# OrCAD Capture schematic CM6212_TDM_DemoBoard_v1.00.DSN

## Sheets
1 04.CS8406: size Custom; title: CS8406; rev: V100; company: C-MEDIA ELECTRONICS Inc.; note: CMA143; note: 6F., 100, Sec. 4, Civil Boulevard, Taipei, Taiwan, R.O.C.
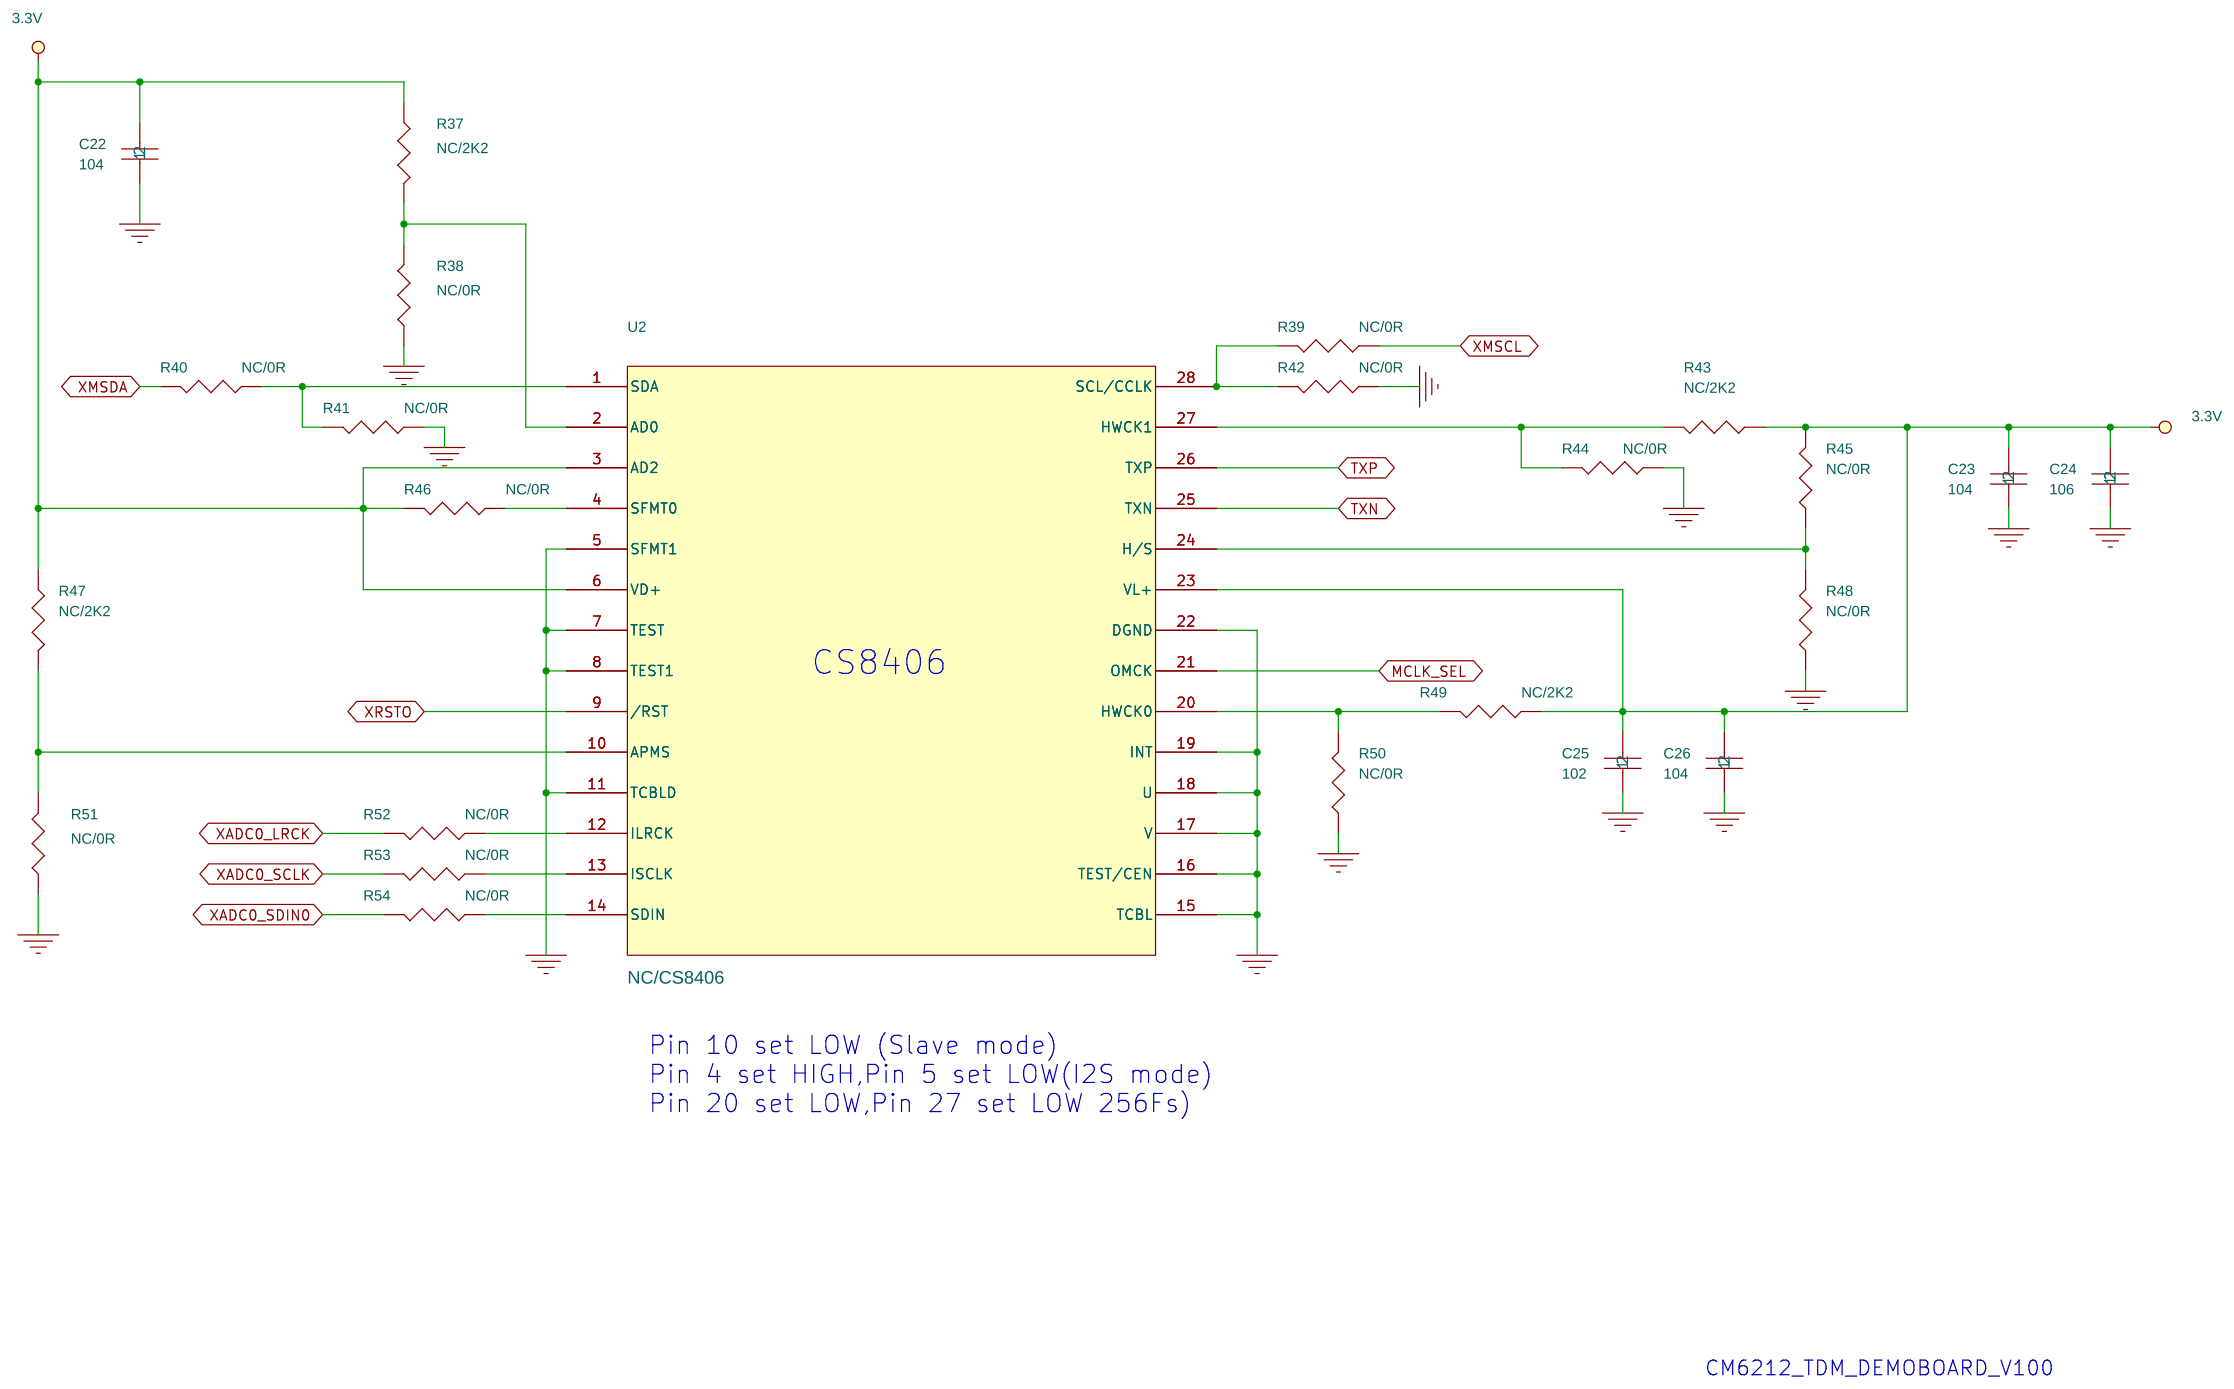
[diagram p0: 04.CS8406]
2 01.FUNCTIONAL BLOCK: title: FUNCTIONAL BLOCK; note: Function block
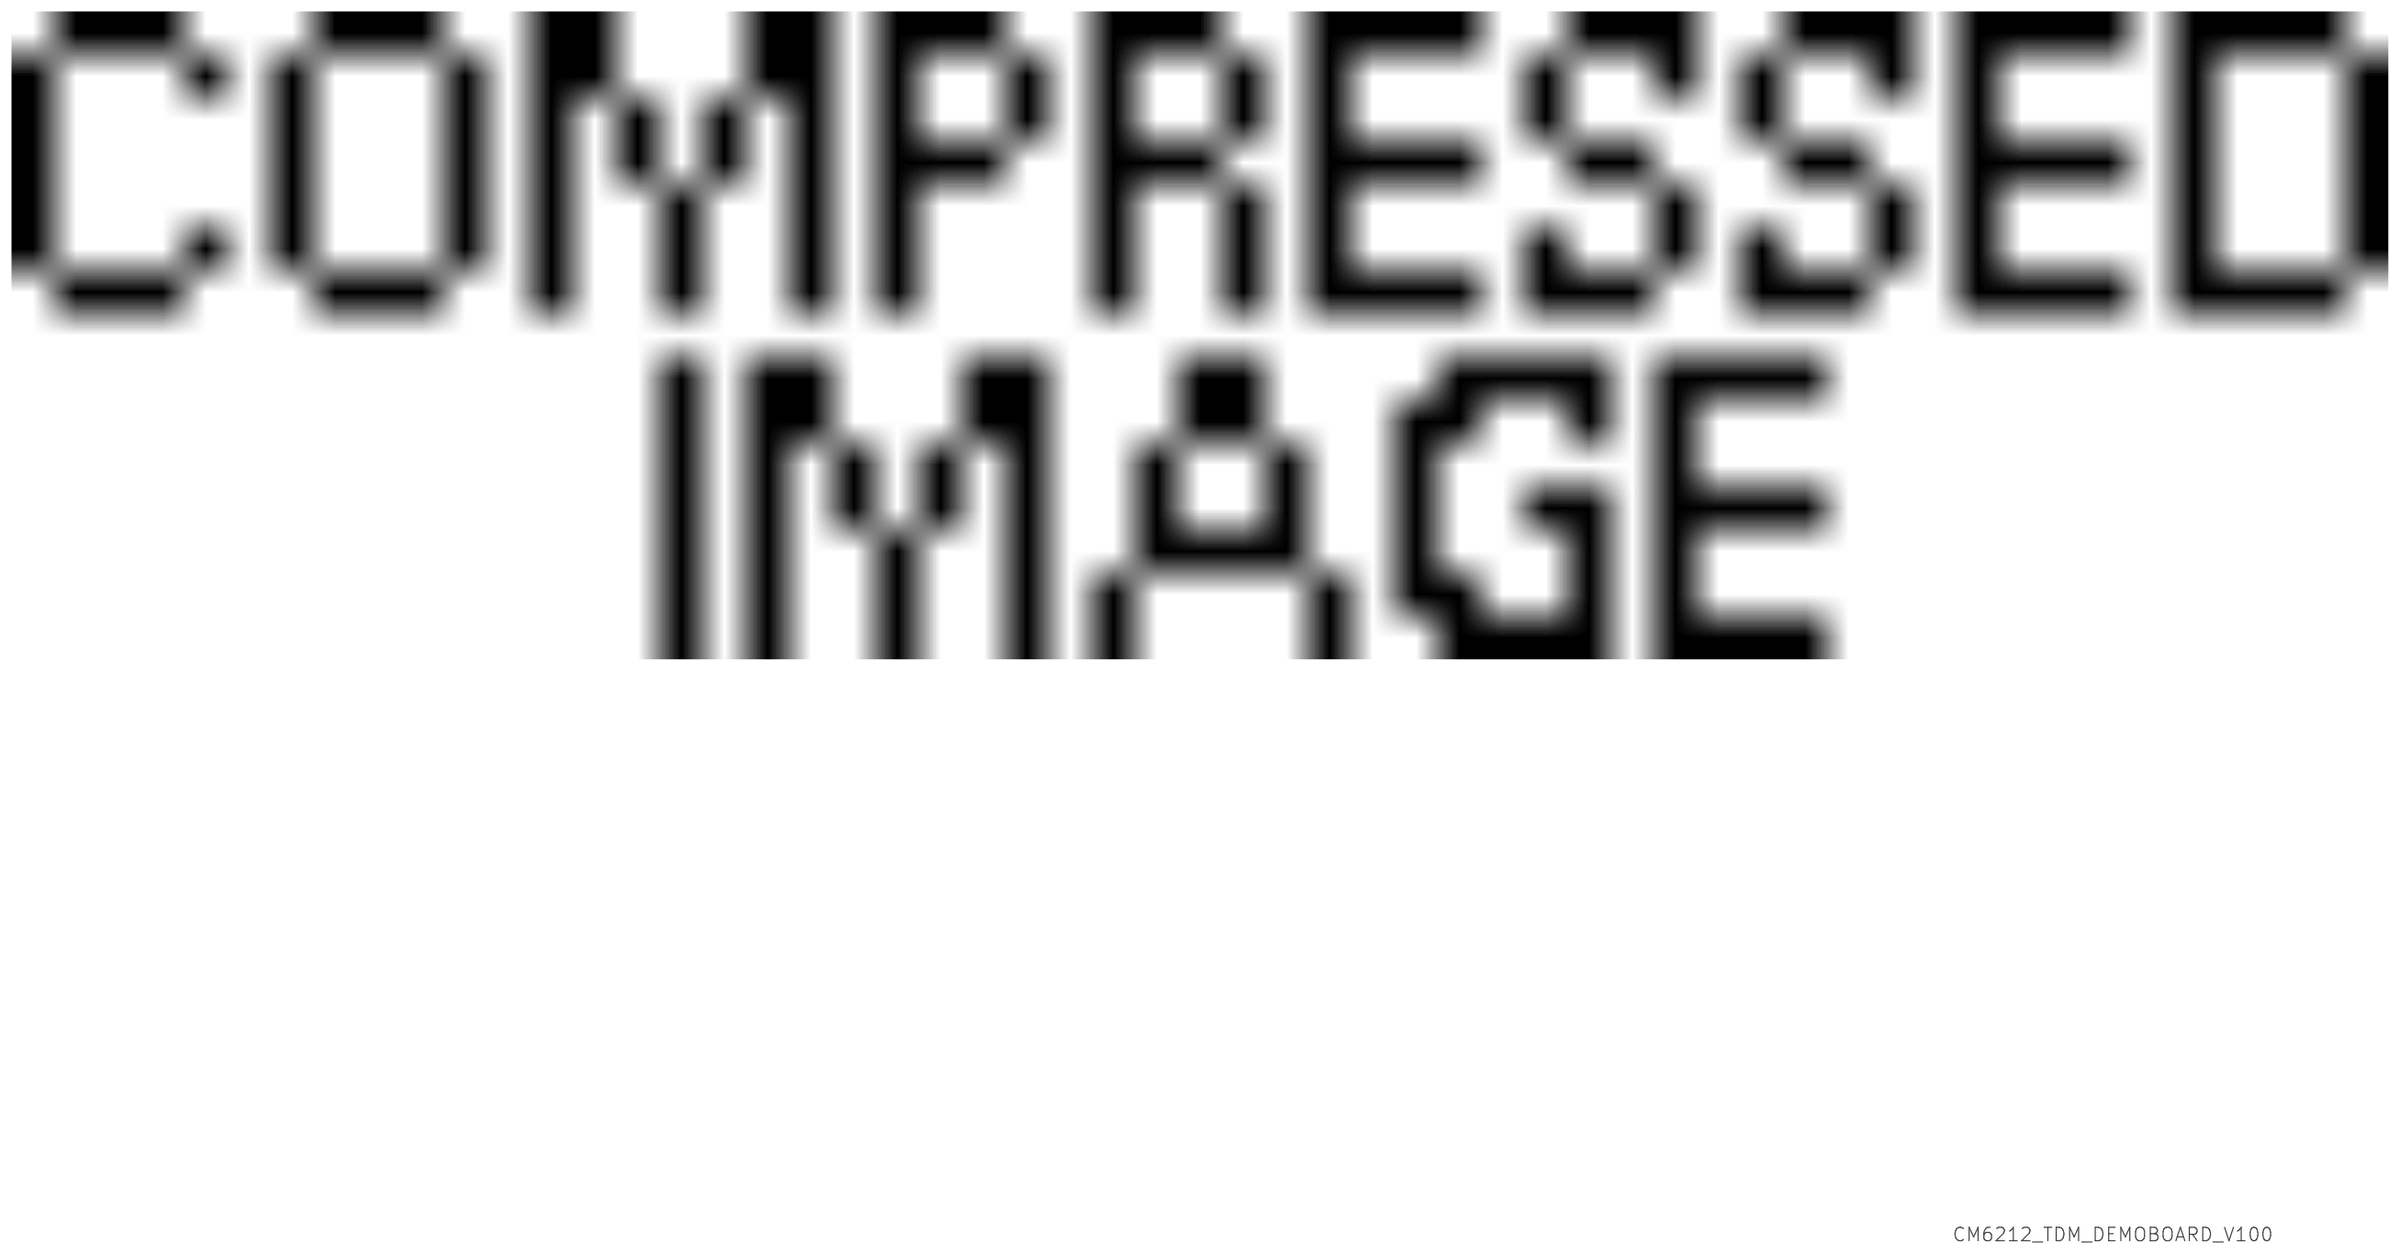
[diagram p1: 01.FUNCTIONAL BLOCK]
3 02.RELEASE NOTE: title: RELEASE NOTE; note: Placement
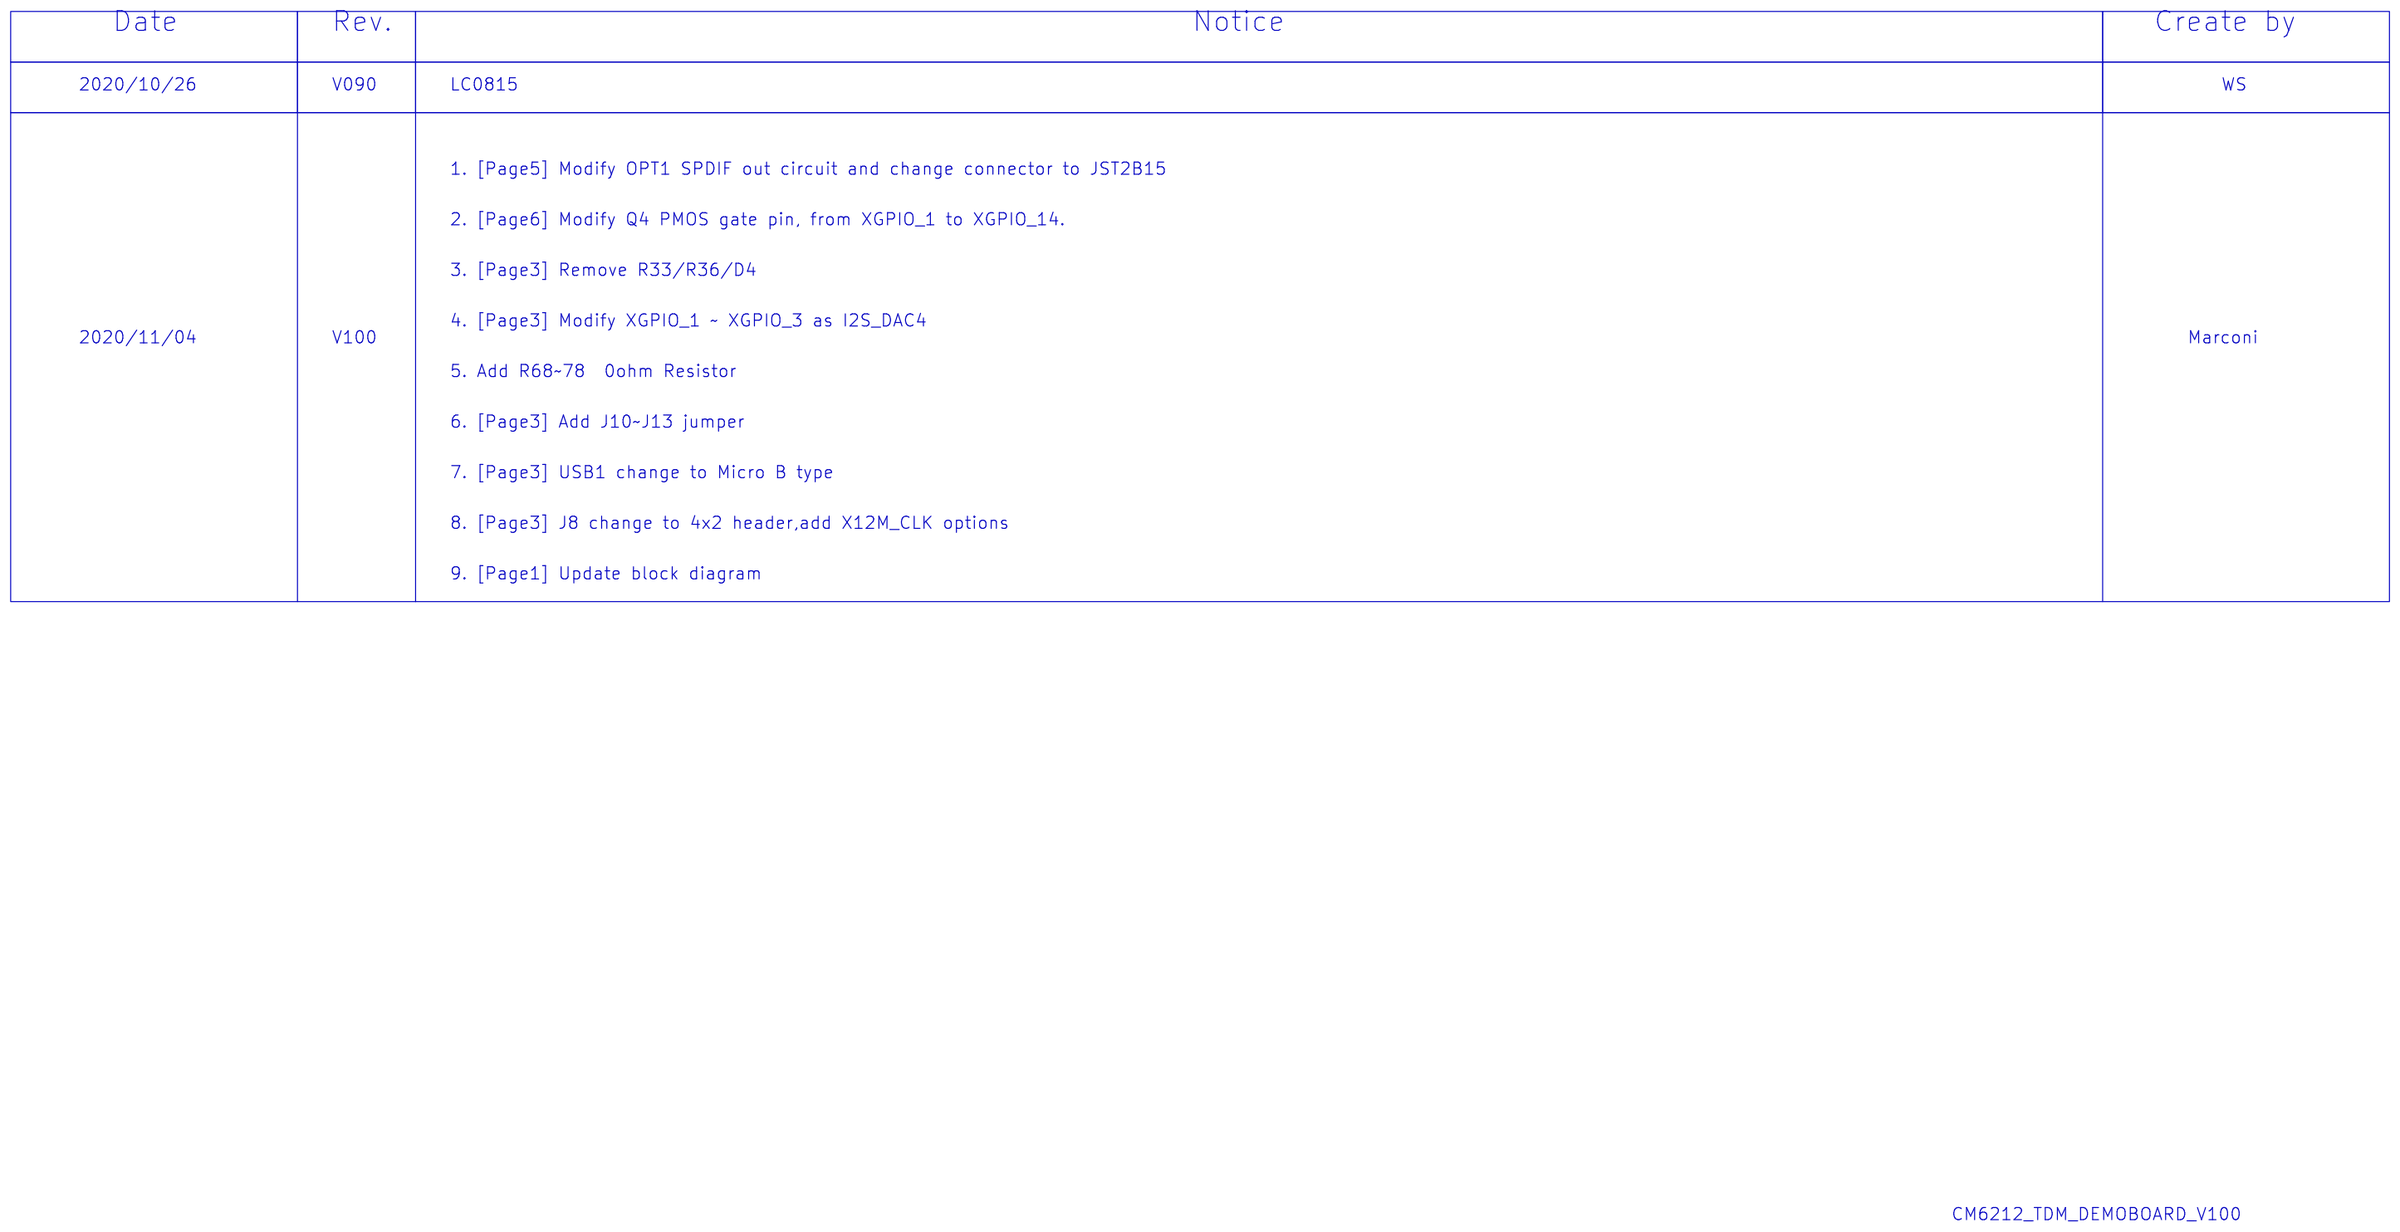
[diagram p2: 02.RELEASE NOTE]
4 03.CM6212: size Custom; title: CM6212
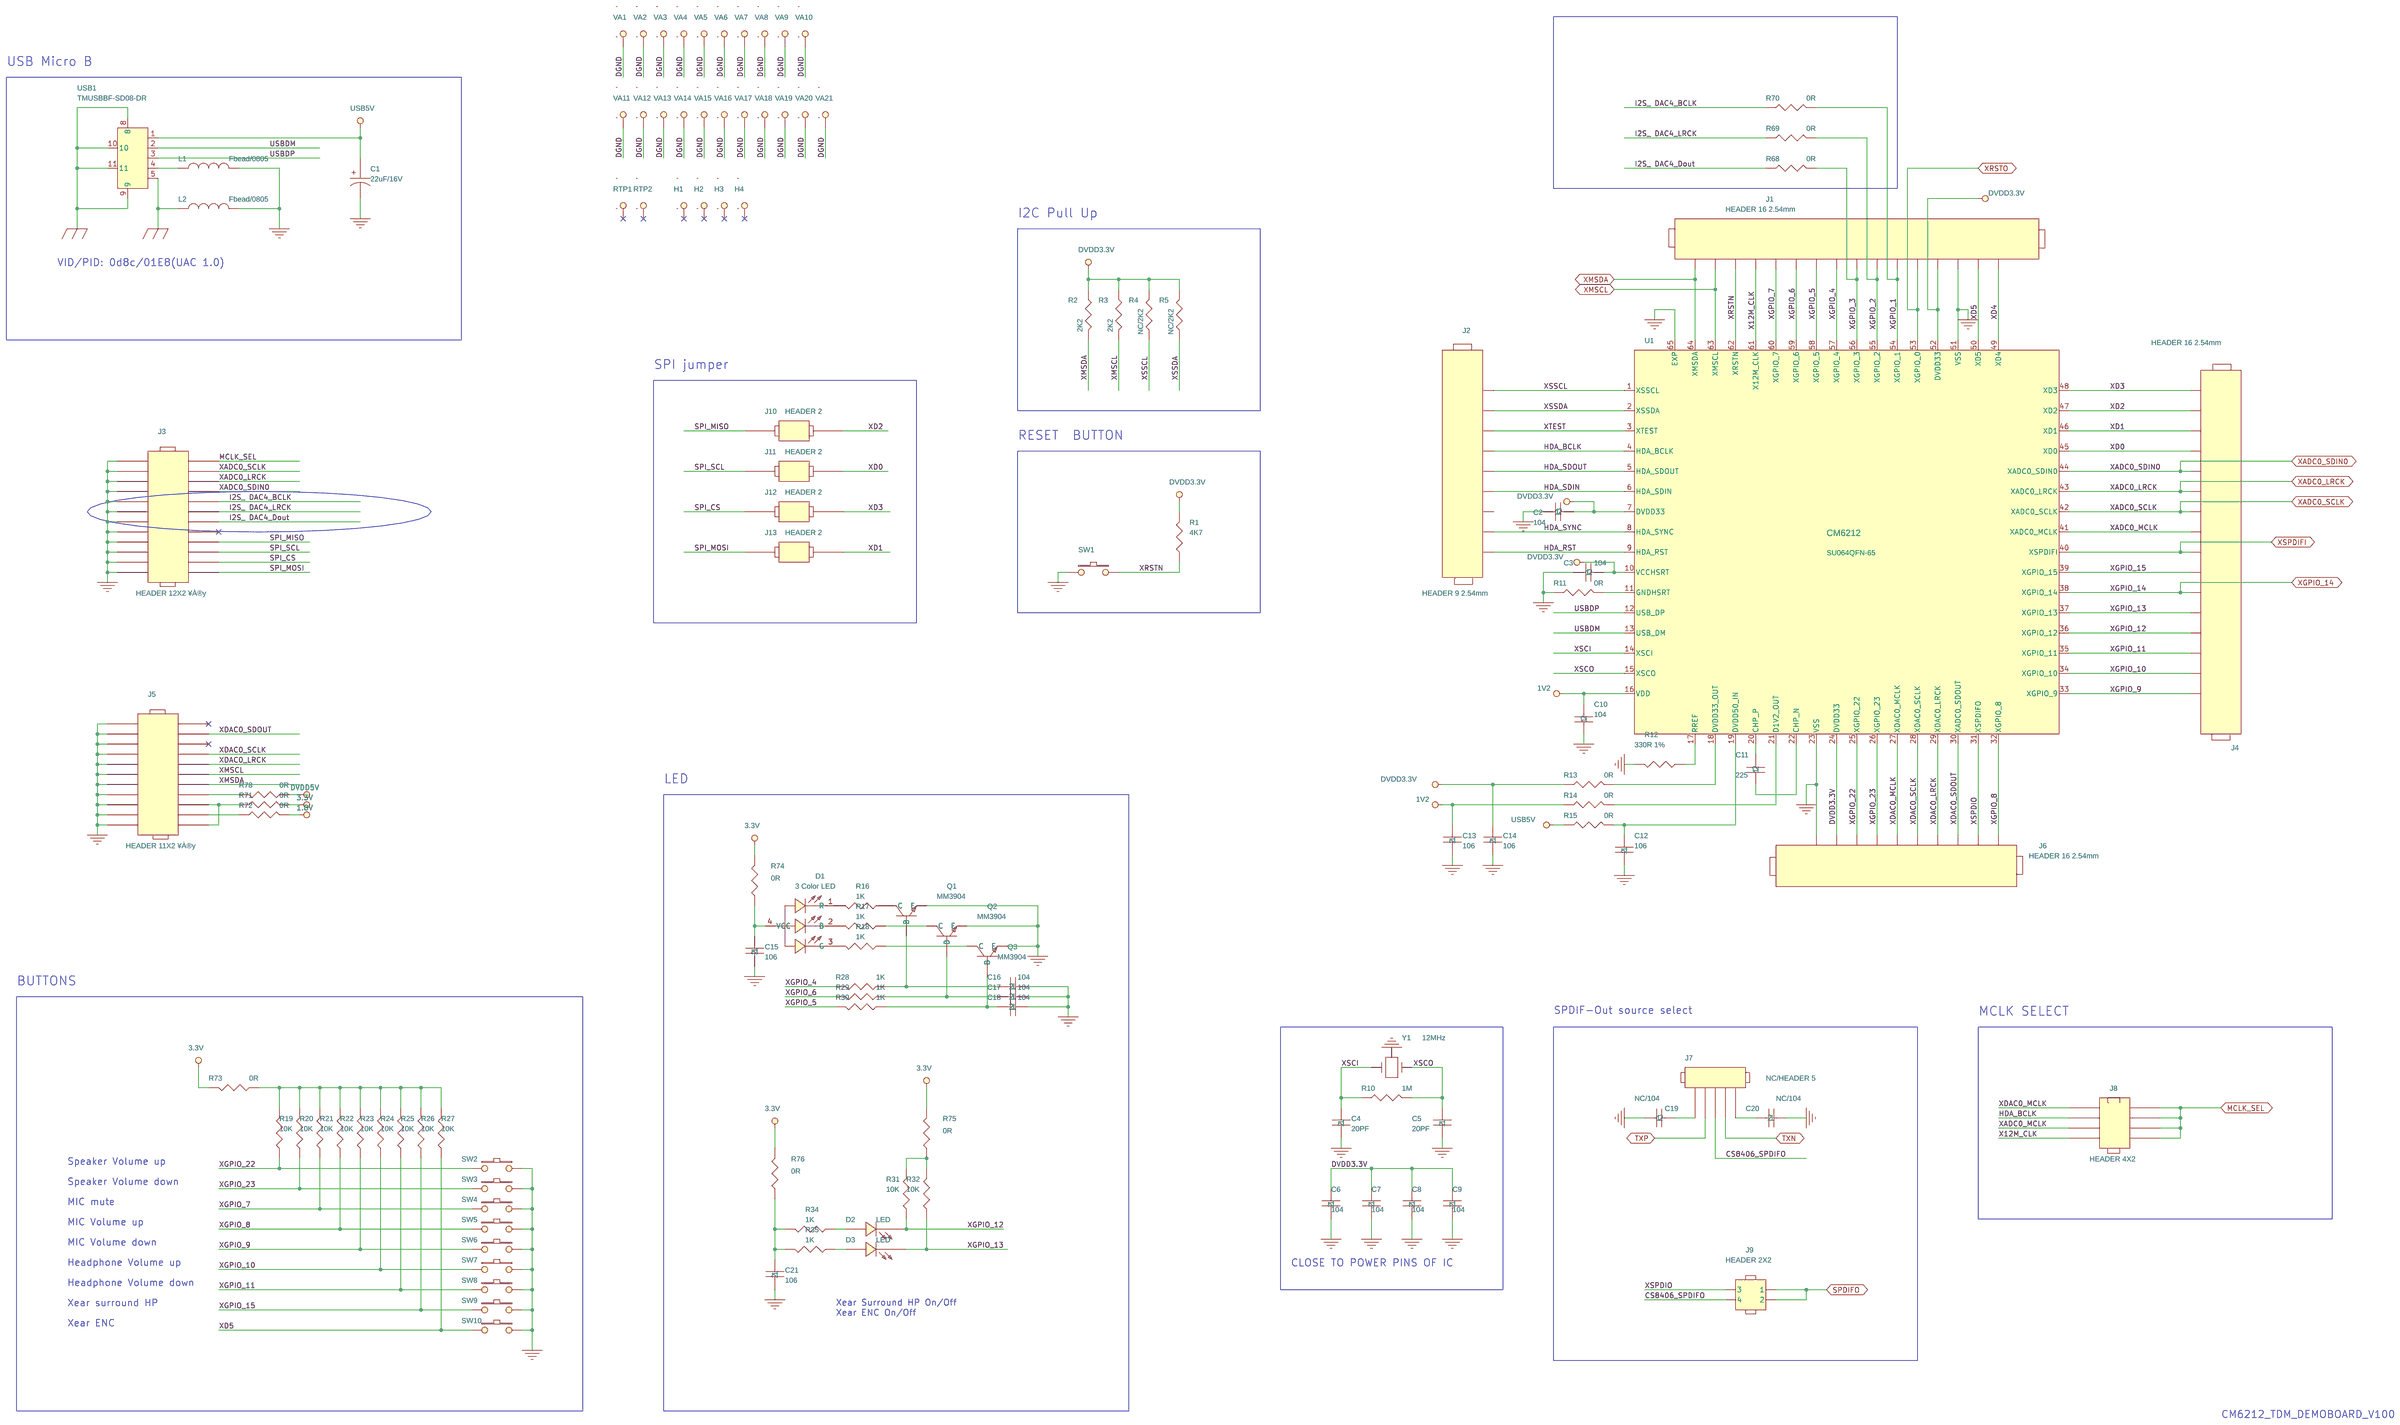
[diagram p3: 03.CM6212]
5 06.POWER: size Custom; title: POWER; note: Power
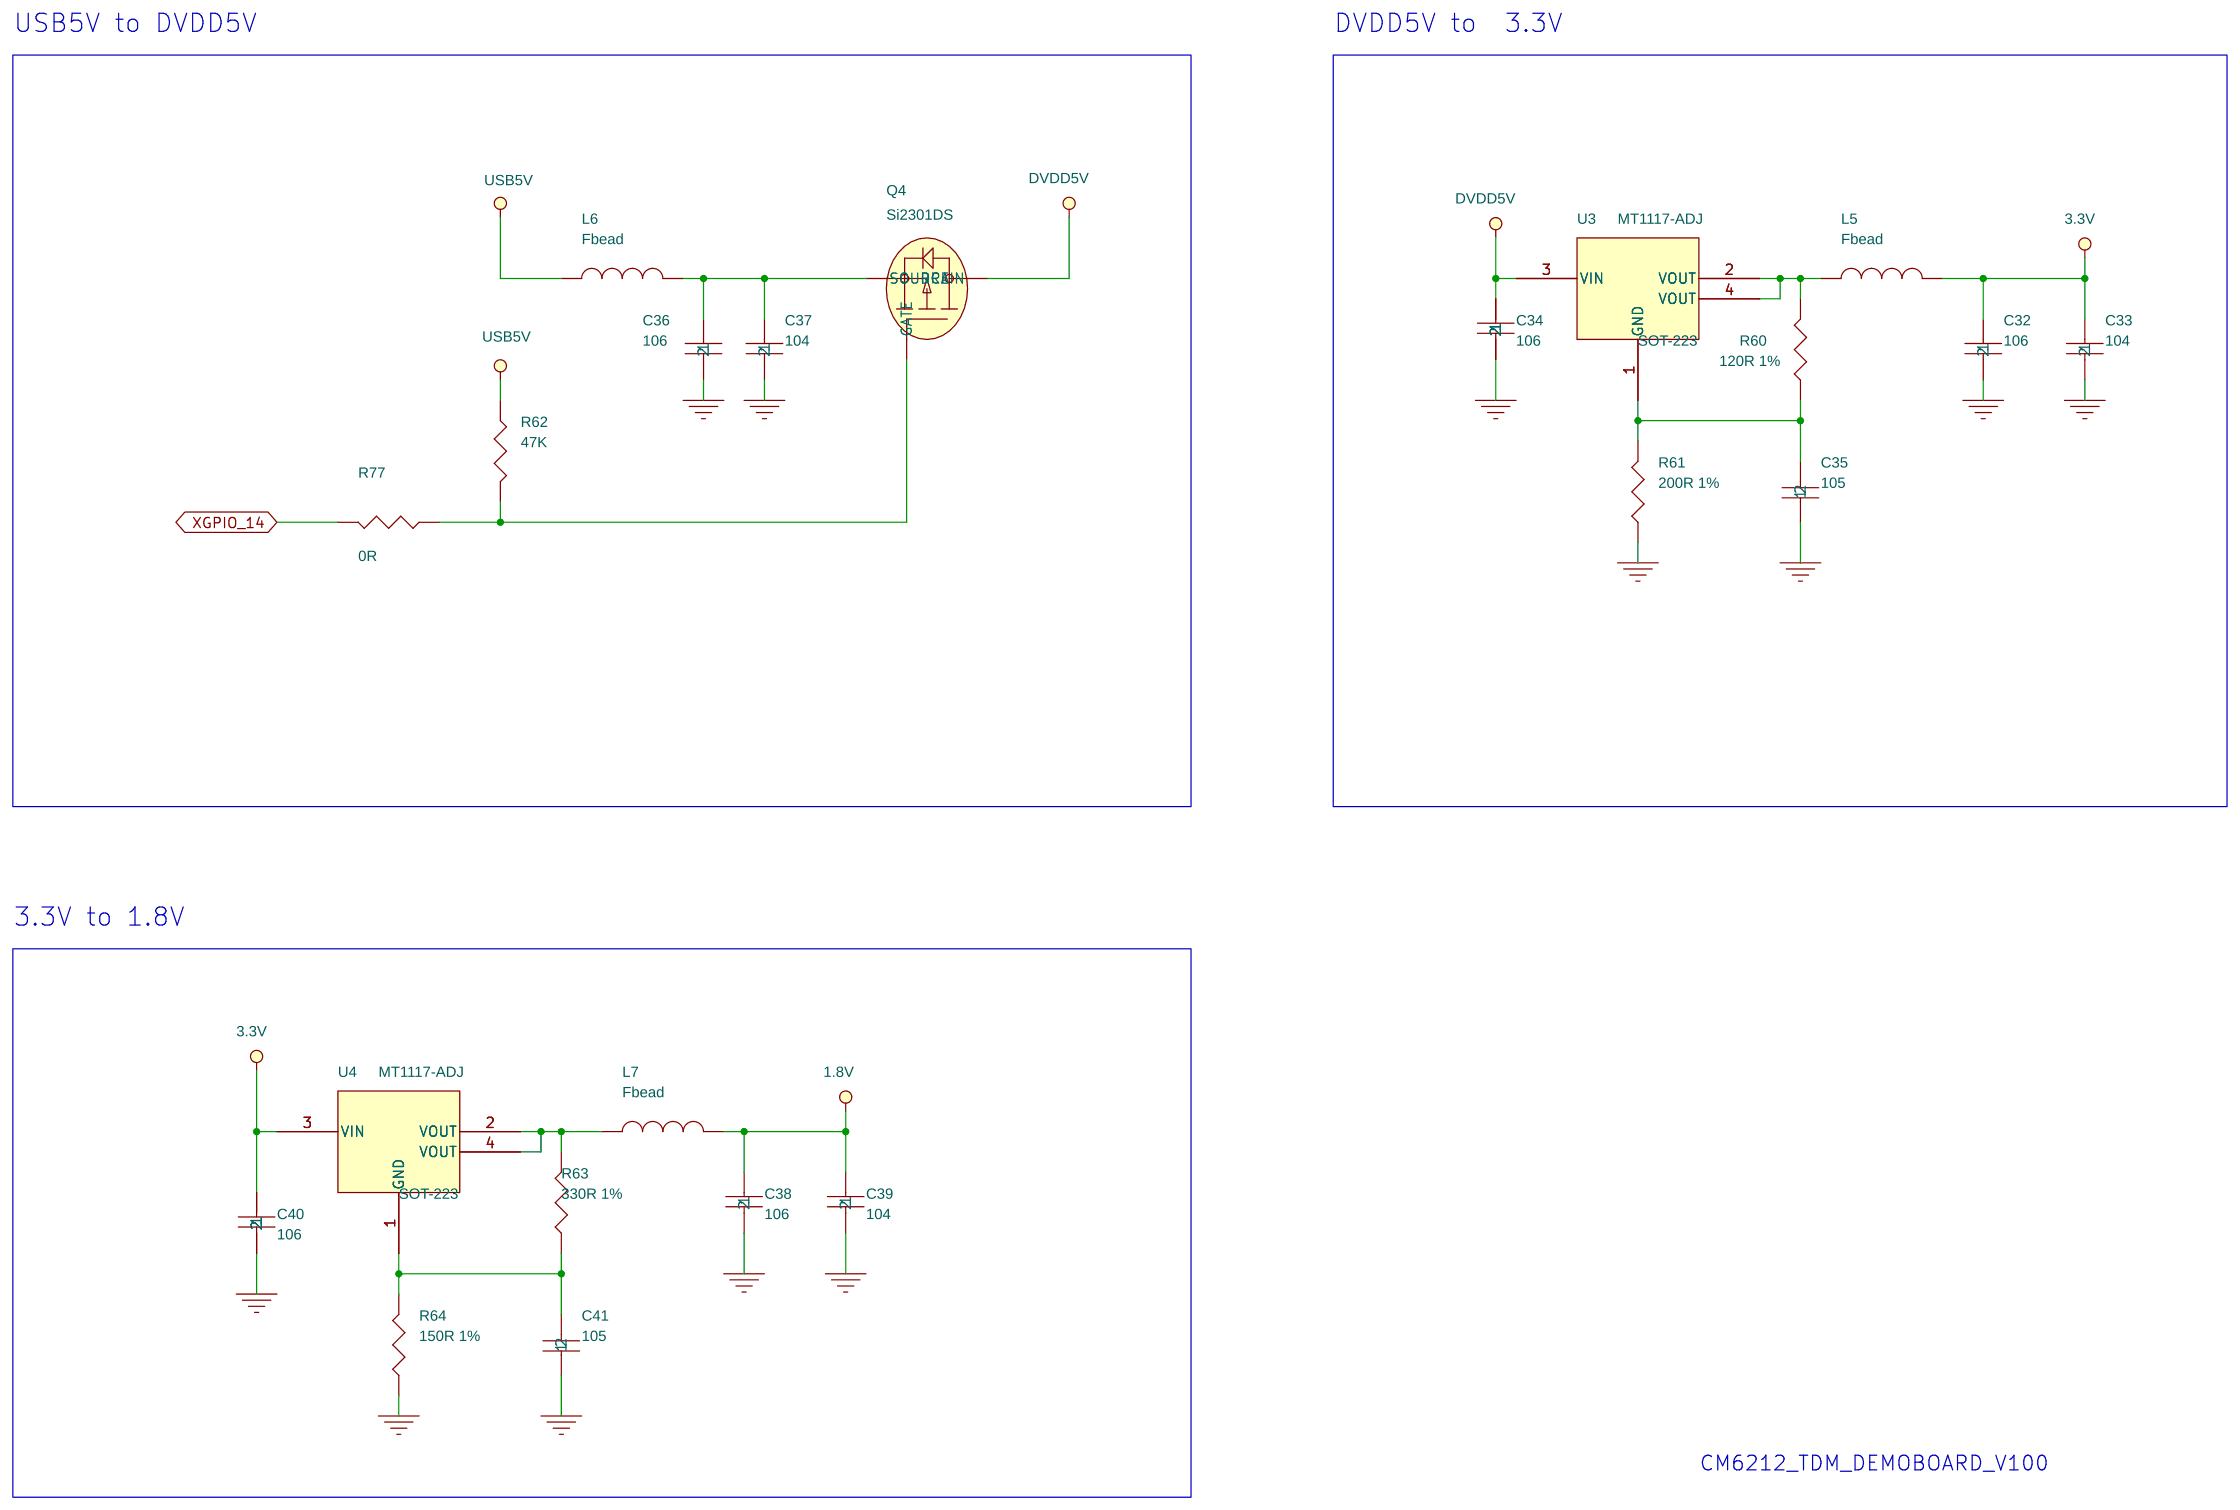
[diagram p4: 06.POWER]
6 05.SPDIF IN/OUT: size Custom; title: SPDIF IN/OUT; note: Power
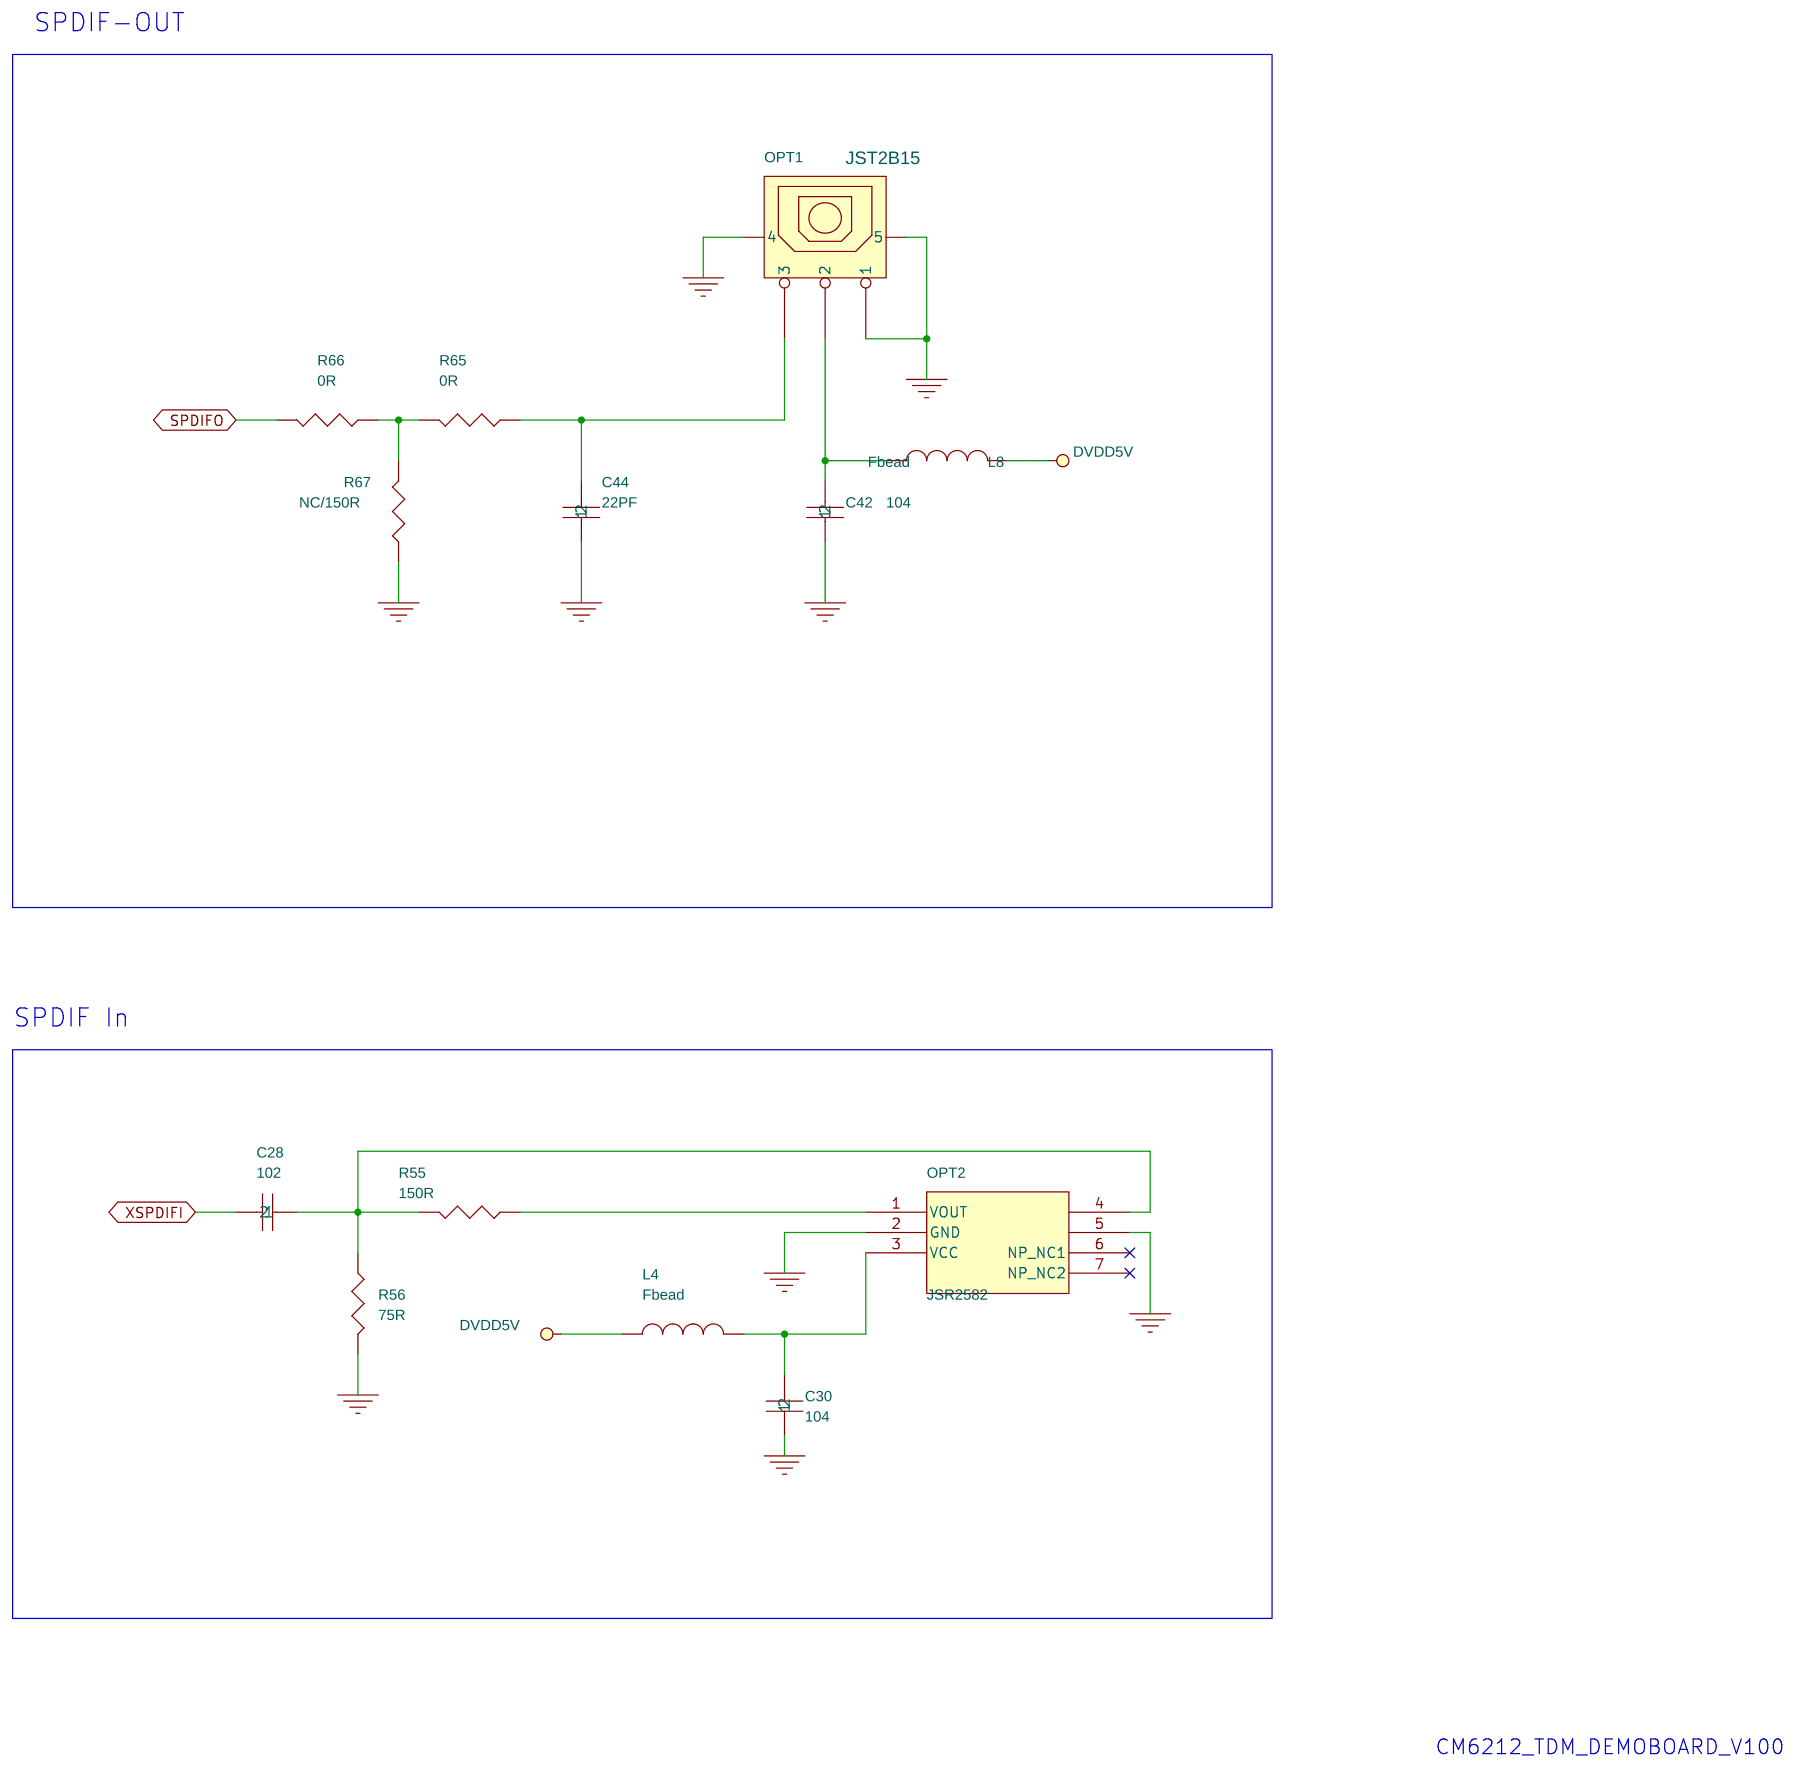
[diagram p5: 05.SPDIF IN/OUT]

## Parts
sheet 03.CM6212
C1  22uF/16V  [DC100C5]
C2  104  [SC0603]
C3  104  [SC0603]
C4  20PF  [SC0603]
C5  20PF  [SC0603]
C6  104  [SC0603]
C7  104  [SC0603]
C8  104  [SC0603]
C9  104  [SC0603]
C10  104  [SC0603]
C11  225  [SC0603]
C12  106  [SC0603]
C13  106  [SC0603]
C14  106  [SC0603]
C15  106  [SC0603]
C16  104  [SC0603]
C17  104  [SC0603]
C18  104  [SC0603]
C19  NC/104  [SC0603]
C20  NC/104  [SC0603]
C21  106  [SC0603]
D1  3 Color LED  [SLED-HG197RGB]
D2  LED  [LED3]
D3  LED  [LED3]
H1  CTT-1135  [HOLE4.0]
H2  CTT-1135  [HOLE4.0]
H3  CTT-1135  [HOLE4.0]
H4  CTT-1135  [HOLE4.0]
J1  HEADER 16 2.54mm  [J1A16]
J2  HEADER 9 2.54mm  [J1A9]
J3  HEADER 12X2 ¥À®y  [J2A24B]
J4  HEADER 16 2.54mm  [J1A16]
J5  HEADER 11X2 ¥À®y  [J2A22B]
J6  HEADER 16 2.54mm  [J1A10]
J7  NC/HEADER 5  [J1A5]
J8  HEADER 4X2  [J2A8A]
J9  HEADER 2X2  [J2A4A]
J10  HEADER 2  [J1A2]
J11  HEADER 2  [J1A2]
J12  HEADER 2  [J1A2]
J13  HEADER 2  [J1A2]
L1  Fbead/0805  [SL0805]
L2  Fbead/0805  [SL0805]
Q1  MM3904  [SOT-23]
Q2  MM3904  [SOT-23]
Q3  MM3904  [SOT-23]
R1  4K7  [SR0603]
R2  2K2  [SR0603]
R3  2K2  [SR0603]
R4  NC/2K2  [SR0603]
R5  NC/2K2  [SR0603]
R10  1M  [SR0603]
R11  0R  [SR0603]
R12  330R 1%  [SR0603]
R13  0R  [SR0603]
R14  0R  [SR0603]
R15  0R  [SR0603]
R16  1K  [SR0603]
R17  1K  [SR0603]
R18  1K  [SR0603]
R19  10K  [SR0603]
R20  10K  [SR0603]
R21  10K  [SR0603]
R22  10K  [SR0603]
R23  10K  [SR0603]
R24  10K  [SR0603]
R25  10K  [SR0603]
R26  10K  [SR0603]
R27  10K  [SR0603]
R28  1K  [SR0603]
R29  1K  [SR0603]
R30  1K  [SR0603]
R31  10K  [SR0603]
R32  10K  [SR0603]
R34  1K  [SR0603]
R35  1K  [SR0603]
R68  0R  [SR0603]
R69  0R  [SR0603]
R70  0R  [SR0603]
R71  0R  [SR0603]
R72  0R  [SR0603]
R73  0R  [SR0603]
R74  0R  [SR0603]
R75  0R  [SR0603]
R76  0R  [SR0603]
R78  0R  [SR0603]
RTP1  CTT-1135  [RTP]
RTP2  CTT-1135  [RTP]
SW1  CTT-1135  [STSW-1135]
SW2  SKRKAEE010  [STSW-1135]
SW3  SKRKAEE010  [STSW-1135]
SW4  SKRKAEE010  [STSW-1135]
SW5  SKRKAEE010  [STSW-1135]
SW6  SKRKAEE010  [STSW-1135]
SW7  SKRKAEE010  [STSW-1135]
SW8  SKRKAEE010  [STSW-1135]
SW9  SKRKAEE010  [STSW-1135]
SW10  SKRKAEE010  [STSW-1135]
U1  CM6212  [SU064QFN-65]
USB1  TMUSBBF-SD08-DR  [MICROUSB5-05S40]
VA1  CTT-1135  [PAD1MM]
VA2  CTT-1135  [PAD.6MM]
VA3  CTT-1135  [PAD.6MM]
VA4  CTT-1135  [PAD.6MM]
VA5  CTT-1135  [PAD.6MM]
VA6  CTT-1135  [PAD.6MM]
VA7  CTT-1135  [PAD.6MM]
VA8  CTT-1135  [PAD.6MM]
VA9  CTT-1135  [PAD.6MM]
VA10  CTT-1135  [PAD.6MM]
VA11  CTT-1135  [PAD.6MM]
VA12  CTT-1135  [PAD.6MM]
VA13  CTT-1135  [PAD.6MM]
VA14  CTT-1135  [PAD.6MM]
VA15  CTT-1135  [PAD.6MM]
VA16  CTT-1135  [PAD.6MM]
VA17  CTT-1135  [PAD.6MM]
VA18  CTT-1135  [PAD.6MM]
VA19  CTT-1135  [PAD.6MM]
VA20  CTT-1135  [PAD.6MM]
VA21  CTT-1135  [PAD.6MM]
Y1  12MHz  [BXS]
sheet 04.CS8406
C22  104  [SC0603]
C23  104  [SC0603]
C24  106  [SC0603]
C25  102  [SC0603]
C26  104  [SC0603]
R37  NC/2K2  [SR0603]
R38  NC/0R  [SR0603]
R39  NC/0R  [SR0603]
R40  NC/0R  [SR0603]
R41  NC/0R  [SR0603]
R42  NC/0R  [SR0603]
R43  NC/2K2  [SR0603]
R44  NC/0R  [SR0603]
R45  NC/0R  [SR0603]
R46  NC/0R  [SR0603]
R47  NC/2K2  [SR0603]
R48  NC/0R  [SR0603]
R49  NC/2K2  [SR0603]
R50  NC/0R  [SR0603]
R51  NC/0R  [SR0603]
R52  NC/0R  [SR0603]
R53  NC/0R  [SR0603]
R54  NC/0R  [SR0603]
U2  NC/CS8406  [SU028TSSOP]
sheet 05.SPDIF IN/OUT
C28  102  [SC0603]
C30  104  [SC0603]
C42  104  [SC0603]
C44  22PF  [SC0603]
L4  Fbead  [SL0805]
L8  Fbead  [SL0805]
OPT1  JST2B15  [JST2B15]
OPT2  JSR2582  [OPT-JST2582]
R55  150R  [SR0603]
R56  75R  [SR0603]
R65  0R  [SR0603]
R66  0R  [SR0603]
R67  NC/150R  [SR0603]
sheet 06.POWER
C32  106  [SC0603]
C33  104  [SC0603]
C34  106  [SC0603]
C35  105  [SC0603]
C36  106  [SC0603]
C37  104  [SC0603]
C38  106  [SC0603]
C39  104  [SC0603]
C40  106  [SC0603]
C41  105  [SC0603]
L5  Fbead  [SL0805]
L6  Fbead  [SL0805]
L7  Fbead  [SL0805]
Q4  Si2301DS  [SOT-23]
R60  120R 1%  [SR0603]
R61  200R 1%  [SR0603]
R62  47K  [SR0603]
R63  330R 1%  [SR0603]
R64  150R 1%  [SR0603]
R77  0R  [SR0603]
U3  MT1117-ADJ  [SOT-223]
U4  MT1117-ADJ  [SOT-223]

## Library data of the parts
C1 = CAPACITOR_POL
C2 = CAP_NP_7
C3 = CAP_NP_15
C4 = CAP_NP_18
C5 C41 = CAP_NP_6
C6 C35 = CAP_NP_5
C7 = CAP_NP_14
C8 C25 C30 C40 = CAP_NP_3
C9 = CAP_NP_12
C10 C24 C32 C44 = CAP_NP_2
C11 C39 = C
C12 = CAP_NP_13
C13 = CAP_NP_16
C14 C26 C36 = CAP_NP_4
C15 = CAP_NP_10
C16 C22 C28 C34 = CAP_NP
C17 = CAP_NP_17
C18 = CAP_NP_8
C19 = CAP_NP_11
C20 C23 C38 C42 = CAP_NP_1
C21 = CAP_NP_9
D1 = LED_5
D2 D3 = LED_0
H1-H4 RTP1 RTP2 VA1-VA21 = SW_PUSHBUTTON_1: 1ST PART FIELD: WAKE UP
J1 J4 = HEADER_54x2_SM_5
J2 = HEADER_54x2_SM_8
J3 = HEADER_12X2
J5 = HEADER_12X2_0
J6 = HEADER_54x2_SM_9
J7 = HEADER_5
J8 = HEADER_3X2_2
J9 = HEADER_2X2_1
J10-J13 = HEADER_5_2
L1 L2 L4-L8 = INDUCTOR
Q1 = MMBT3904_SOT_2
Q2 = MMBT3904_SOT_1
Q3 = MMBT3904_SOT_0
R1-R5 R10-R32 R34 R35 R37-R56 R60-R78 = R
SW1 = SW_PUSHBUTTON: 1ST PART FIELD: WAKE UP
SW2-SW10 = SW_PUSHBUTTON
U1 = CMI120_103
USB1 = HEADER_4_2: 1ST PART FIELD: USB Micro B-Type SMD
Y1 = ZTA_0
U2 = PIC16F1937-I_PT_8
OPT1 = HEADER_3_2: 1ST PART FIELD: TOTX178
OPT2 = OPTICAL_MDL_JACK_5P_2HOLD: Class: IO; Colay_Alternate: N/A; Device: optcl_mdl_jack_5p_2h_lf3; Electric_SPE: BLACK; Package_Type: DIP; Part Number: 12G146301057; Symbol_pic: K:\Symbol_Pic\12-CONNECTOR\12G146301057_MID.zip
C33 = C_1
C37 = C_2
Q4 = PWRMOSFET_EP_GSD_4
U3 = AIC1117_SOT223_6
U4 = AIC1117_SOT223_7

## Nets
1.8V: C38.1 C39.1 L7.2 R72.2
1V2: C10.2 C13.1 R14.1 U1.16(VDD)
3.3V: C22.2 C23.2 C24.2 C25.2 C26.2 C32.1 C33.1 C40.1 L5.2 R37.1 R43.1 R45.2 R46.2 R47.1 R49.1 R71.2 R73.2 R74.2 R75.2 R76.2 U2.3(AD2) U2.6(VD+) U2.23(VL+) U4.3(VIN)
DGND: C1.2 C2.1 C3.1 C4.2 C5.2 C6.2 C7.2 C8.2 C9.2 C10.1 C12.2 C13.2 C14.2 C15.2 C16.1 C17.1 C18.1 C19.1 C20.1 C21.2 C22.1 C23.1 C24.1 C25.1 C26.1 C30.1 C32.2 C33.2 C34.2 C35.1 C36.2 C37.2 C38.2 C39.2 C40.2 C41.1 C42.1 C44.1 J1.3 J3.1 J3.3 J3.5 J3.7 J3.9 J3.11 J3.13 J3.15 J3.17 J3.19 J3.21 J3.23 J5.1 J5.3 J5.5 J5.7 J5.9 J5.11 J5.13 J5.15 J5.17 J5.19 J5.21 J6.1 L1.1 L2.1 OPT1.1 OPT1.4 OPT1.5 OPT2.2(GND) OPT2.5 Q1.2(E) Q2.2(E) Q3.2(E) R11.1 R12.2 R38.1 R41.1 R42.1 R44.1 R48.1 R50.1 R51.1 R56.2 R61.1 R64.1 R67.2 SW1.2 SW2.1 SW3.1 SW4.1 SW5.1 SW6.1 SW7.1 SW8.1 SW9.1 SW10.1 U1.23(VSS) U1.51(VSS) U1.65(EXP) U2.5(SFMT1) U2.7(TEST) U2.8(TEST1) U2.11(TCBLD) U2.15(TCBL) U2.16(TEST/CEN) U2.17(V) U2.18(U) U2.19(INT) U2.22(DGND) VA1.1 VA2.1 VA3.1 VA4.1 VA5.1 VA6.1 VA7.1 VA8.1 VA9.1 VA10.1 VA11.1 VA12.1 VA13.1 VA14.1 VA15.1 VA16.1 VA17.1 VA18.1 VA19.1 VA20.1 VA21.1 Y1.3
DVDD3.3V: C2.2 C3.2 C6.1 C7.1 C8.1 C9.1 C14.1 J1.4 J6.2 R1.2 R2.1 R3.1 R4.1 R5.1 R13.1 U1.7(DVDD33) U1.10(VCCHSRT) U1.24(DVDD33) U1.52(DVDD33)
DVDD5V: C34.1 L4.2 L8.1 Q4.3(DRAIN) R78.1 U3.3(VIN)
GND_EARTH: L2.2 USB1.5 USB1.8 USB1.9 USB1.10 USB1.11
CS8406_SPDIFO: J7.3 J9.3(4)
HDA_BCLK: J2.4 J8.3 U1.4(HDA_BCLK)
HDA_RST: J2.9 U1.9(HDA_RST)
HDA_SDIN: J2.6 U1.6(HDA_SDIN)
HDA_SDOUT: J2.5 U1.5(HDA_SDOUT)
HDA_SYNC: J2.8 U1.8(HDA_SYNC)
I2S_ DAC4_BCLK: J3.10 R70.1
I2S_ DAC4_Dout: J3.14 R68.1
I2S_ DAC4_LRCK: J3.12 R69.1
MCLK_SEL: J3.2 J8.2 J8.4 J8.6 J8.8 U2.21(OMCK)
SPDIFO: J9.2(1) J9.4(2) R66.2
SPI_CS: J3.22 J12.1
SPI_MISO: J3.18 J10.1
SPI_MOSI: J3.24 J13.1
SPI_SCL: J3.20 J11.1
TXN: J7.2 U2.25(TXN)
TXP: J7.4 U2.26(TXP)
USB5V: C1.1 L6.1 R15.1 R62.1 USB1.1
USBDM: U1.13(USB_DM) USB1.2
USBDP: U1.12(USB_DP) USB1.3
X12M_CLK: J1.13 J8.7 U1.61(X12M_CLK)
XADC0_LRCK: J3.6 J4.11 R52.2 U1.43(XADC0_LRCK)
XADC0_MCLK: J4.9 J8.5 U1.41(XADC0_MCLK)
XADC0_SCLK: J3.4 J4.10 R53.2 U1.42(XADC0_SCLK)
XADC0_SDIN0: J3.8 J4.12 R54.2 U1.44(XADC0_SDIN0)
XD0: J4.13 J11.2 U1.45(XD0)
XD1: J4.14 J13.2 U1.46(XD1)
XD2: J4.15 J10.2 U1.47(XD2)
XD3: J4.16 J12.2 U1.48(XD3)
XD4: J1.1 U1.49(XD4)
XD5: J1.2 R27.1 SW10.2 U1.50(XD5)
XDAC0_LRCK: J5.10 J6.7 U1.29(XDAC0_LRCK)
XDAC0_MCLK: J6.5 J8.1 U1.27(XDAC0_MCLK)
XDAC0_SCLK: J5.8 J6.6 U1.28(XDAC0_SCLK)
XDAC0_SDOUT: J5.4 J6.8 U1.30(XADC0_SDOUT)
XGPIO_1: J1.6 R70.2 U1.54(XGPIO_1)
XGPIO_2: J1.7 R69.2 U1.55(XGPIO_2)
XGPIO_3: J1.8 R68.2 U1.56(XGPIO_3)
XGPIO_4: J1.9 R28.1 U1.57(XGPIO_4)
XGPIO_5: J1.10 R30.1 U1.58(XGPIO_5)
XGPIO_6: J1.11 R29.1 U1.59(XGPIO_6)
XGPIO_7: J1.12 R21.1 SW4.2 U1.60(XGPIO_7)
XGPIO_8: J6.10 R22.1 SW5.2 U1.32(XGPIO_8)
XGPIO_9: J4.1 R23.1 SW6.2 U1.33(XGPIO_9)
XGPIO_10: J4.2 R24.1 SW7.2 U1.34(XGPIO_10)
XGPIO_11: J4.3 R25.1 SW8.2 U1.35(XGPIO_11)
XGPIO_12: D2.2(CATHODE) J4.4 R31.1 U1.36(XGPIO_12)
XGPIO_13: D3.2(CATHODE) J4.5 R32.1 U1.37(XGPIO_13)
XGPIO_14: J4.6 R77.2 U1.38(XGPIO_14)
XGPIO_15: J4.7 R26.1 SW9.2 U1.39(XGPIO_15)
XGPIO_22: J6.3 R19.1 SW2.2 U1.25(XGPIO_22)
XGPIO_23: J6.4 R20.1 SW3.2 U1.26(XGPIO_23)
XMSCL: J1.15 J5.12 R3.2 R39.1 U1.63(XMSCL)
XMSDA: J1.16 J5.14 R2.2 R40.2 U1.64(XMSDA)
XRSTN: J1.14 R1.1 SW1.1 U1.62(XRSTN)
XRSTO: J1.5 U1.53(XGPIO_0) U2.9(/RST)
XSCI: C4.1 R10.1 U1.14(XSCI) Y1.1
XSCO: C5.1 R10.2 U1.15(XSCO) Y1.2
XSPDIFI: C28.2 J4.8 U1.40(XSPDIFI)
XSPDIO: J6.9 J9.1(3) U1.31(XSPDIFO)
XSSCL: J2.1 R4.2 U1.1(XSSCL)
XSSDA: J2.2 R5.2 U1.2(XSSDA)
XTEST: J2.3 U1.3(XTEST)
N30417151: C28.1 OPT2.4 R55.2 R56.1
N30417199: OPT2.1(VOUT) R55.1
N30435382: C42.2 L8.2 OPT1.2
N30435419: C44.2 OPT1.3 R65.1
N30438111: R11.2 U1.11(GNDHSRT)
N30438169: R12.1 U1.17(RREF)
N30438171: R13.2 U1.18(DVDD33_OUT)
N30438173: C12.1 R15.2 U1.19(DVDD50_IN)
N30438175: C11.2 U1.20(CHP_P)
N30438177: R14.2 U1.21(D1V2_OUT)
N30438179: C11.1 U1.22(CHP_N)
N30439733: C19.2 J7.5
N30439741: C20.2 J7.1
N30441072: C15.1 D1.4(VCC) R74.1
N30441099: Q2.3(C) R17.2
N30441122: C16.2 Q1.1(B) R28.2
N30441132: Q3.3(C) R18.2
N30441147: C17.2 Q2.1(B) R29.2
N30441163: C18.2 Q3.1(B) R30.2
N30441277: R31.2 R32.2 R75.1
N30441299: C21.1 R34.1 R35.1 R76.1
N30441325: D2.1(ANODE) R34.2
N30441350: D3.1(ANODE) R35.2
N30443652: L1.2 USB1.4
N30443902: J5.16 R78.2
N30443920: J5.18 J5.22 R71.1
N30443944: J5.20 R72.1
N30444947: R19.2 R20.2 R21.2 R22.2 R23.2 R24.2 R25.2 R26.2 R27.2 R73.1
N30446649: C30.2 L4.1 OPT2.3(VCC)
N30448109: C36.1 C37.1 L6.2 Q4.2(SOURCE)
N30448141: Q4.1(GATE) R62.2 R77.1
N30449769: L5.1 R60.2 U3.2(VOUT) U3.4(VOUT)
N30449823: C35.2 R60.1 R61.2 U3.1(GND)
N30450073: L7.1 R63.2 U4.2(VOUT) U4.4(VOUT)
N30450125: C41.2 R63.1 R64.2 U4.1(GND)
N30462035: R37.2 R38.2 U2.2(AD0)
N30462102: R39.2 R42.2 U2.28(SCL/CCLK)
N30462135: R40.1 R41.2 U2.1(SDA)
N30462173: R43.2 R44.2 U2.27(HWCK1)
N30462267: R46.1 U2.4(SFMT0)
N30462277: R45.1 R48.2 U2.24(H/S)
N30462326: R47.2 R51.2 U2.10(APMS)
N30462353: R49.2 R50.2 U2.20(HWCK0)
N30462440: R52.1 U2.12(ILRCK)
N30462465: R53.1 U2.13(ISCLK)
N30462488: R54.1 U2.14(SDIN)
N30473868: R65.2 R66.1 R67.1
N30477718: D1.2(B) R17.1
N30477719: D1.3(G) R18.1
N30477720: Q1.3(C) R16.2
N30477721: D1.1(R) R16.1

Not connected (* = marked no-connect by the designer): H1 1*; H2 1*; H3 1*; H4 1*; J2 7; J3 16*; J5 2* 6*; OPT2 6(NP_NC1)* 7(NP_NC2)*; RTP1 1*; RTP2 1*

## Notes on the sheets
sheet 1
- CS8406
- Pin 10 set LOW (Slave mode)
  Pin 4 set HIGH,Pin 5 set LOW(I2S mode)
  Pin 20 set LOW,Pin 27 set LOW 256Fs)
- CM6212_TDM_DEMOBOARD_V100
sheet 2
- CM6212_TDM_DEMOBOARD_V100
sheet 3
- Date
- Rev.
- Notice
- Create by
- 2020/10/26
- V090
- LC0815
- WS
- 1. [Page5] Modify OPT1 SPDIF out circuit and change connector to JST2B15
- 2. [Page6] Modify Q4 PMOS gate pin, from XGPIO_1 to XGPIO_14.
- 3. [Page3] Remove R33/R36/D4
- 4. [Page3] Modify XGPIO_1 ~ XGPIO_3 as I2S_DAC4
- 2020/11/04
- V100
- Marconi
- 5. Add R68~78  0ohm Resistor
- 6. [Page3] Add J10~J13 jumper
- 7. [Page3] USB1 change to Micro B type
- 8. [Page3] J8 change to 4x2 header,add X12M_CLK options
- 9. [Page1] Update block diagram
- CM6212_TDM_DEMOBOARD_V100
sheet 4
- USB Micro B
- I2C Pull Up
- VID/PID: 0d8c/01E8(UAC 1.0)
- SPI jumper
- RESET  BUTTON
- LED
- BUTTONS
- SPDIF-Out source select
- MCLK SELECT
- Speaker Volume up
- Speaker Volume down
- MIC mute
- MIC Volume up
- MIC Volume down
- Headphone Volume up
- CLOSE TO POWER PINS OF IC
- Headphone Volume down
- Xear surround HP
- Xear Surround HP On/Off
- Xear ENC On/Off
- Xear ENC
- CM6212_TDM_DEMOBOARD_V100
sheet 5
- USB5V to DVDD5V
- DVDD5V to  3.3V
- 3.3V to 1.8V
- CM6212_TDM_DEMOBOARD_V100
sheet 6
- SPDIF-OUT
- SPDIF In
- CM6212_TDM_DEMOBOARD_V100
